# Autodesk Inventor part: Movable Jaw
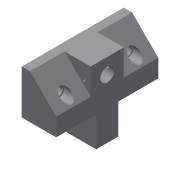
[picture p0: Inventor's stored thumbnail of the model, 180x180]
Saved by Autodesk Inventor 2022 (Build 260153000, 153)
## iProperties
Created: 2002-02
Part Number: Movable Jaw
Document SubType Name: Modeling
Designer: ***
Density: 1 g/cm^3
Material: Generic
Appearance: Default
Control State: 0
Master: False
Checked Out: False
Shininess: 77.0
Length Units: 11269
Angle Units: 11279
Time Units: 11290
Mass Units: 11283
Length Display Precision: 3
Angle Display Precision: 2
Density: 0.0
Volumn: 0.0
Area: 0.0
PropertySet Name: Model Information
Author: ***
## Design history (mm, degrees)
sketch "Sketch2"
  geometry: L1 (2.39, 41.509)-(2.39, 9.509); L2 (2.39, 9.509)-(-22.61, 9.509); L3 (-22.61, 9.509)-(-22.61, 22.509); L4 (-22.61, 22.509)-(-3.61, 41.509); L5 (-3.61, 41.509)-(2.39, 41.509)
  constraints: 10 end point, 2 parallel, 1 perpendicular, 1 vertical
  dimensions: "d0" = 25 distance of L1.end L2.end; "d2" = 13 distance of L2.end L3.end; "d3" = 32 distance between parallel lines of L5 L2; "d4" = 6 distance of L4.end L1.start
extrude "Extrusion1" new body sketch "Sketch2" stored distance "d5" = 74; taper "d6" = 0 deg
sketch "Sketch3"
  geometry: L1 (-19, 25)-(11, 25); L2 (11, 25)-(11, 49); L3 (11, 49)-(-19, 49); L4 (-19, 49)-(-19, 25); L5 (0, 0)-(13, 0) reference; L6 (-19, 74)-(-19, 0) reference; L7 (11.924, 29)-(35, 29); L8 (35, 29)-(35, 45); L9 (35, 45)-(11.924, 45); L10 (11.924, 45)-(11.924, 29); L11 (13, 74)-(13, 0) reference
  constraints: 16 end point, 4 parallel, 2 horizontal, 2 perpendicular, 1 collinear
  dimensions: "d7" = 24 distance of L3.end L1.start; "d8" = 30 distance of L1.start L1.end; "d9" = 25 distance between parallel lines of L5 L1; "d10" = 16 distance of L7.end L8.end; "d11" = 4 distance between parallel lines of L3 L9; "d12" = 22 distance between parallel lines of L11 L8
extrude "Extrusion2" join sketch "Sketch3" distance "d13" = 25; taper "d14" = 0 deg
sketch "Sketch4"
  geometry: L1 (-19, -25)-(-19, -49) reference; L2 (-19, -49)-(0, -49) reference; 1 further point
  dimensions: "d15" = 11 distance from line of L1 point (-8, -37); "d16" = 12 distance from line of L2 point (-8, -37)
hole "Hole1" sketch "Sketch4" at (-8, -37) diameter "d17" = 10; stored, may be unused: countersink angle "d21" = 82 deg, drill point angle "d23" = 0 deg; dims "d18" = 6, "d19" = 4, "d20" = 2, "d22" = 13
sketch "Sketch5"
  geometry: L1 (-19, -49)-(-19, -74) reference; L2 (0, -74)-(13, -74) reference; 1 further point
  dimensions: "d24" = 14 distance from line of L1 point (-5, -62); "d25" = 12 distance from line of L2 point (-5, -62)
hole "Hole2" sketch "Sketch5" at (-5, -62) diameter "d26" = 6; stored, may be unused: countersink angle "d30" = 82 deg, drill point angle "d32" = 0 deg; dims "d27" = 6, "d28" = 8, "d29" = 10, "d31" = 13
mirror "Mirror1"
sketch "Sketch6"
  geometry: L1 (0, 19)-(0, 0) reference; 1 further point
  dimensions: "d33" = 5 distance from line of L1 point (-5, 8); "d34" = 11 vertical distance of L1.start point (-5, 8)
hole "Hole3" sketch "Sketch6" at (-5, 8) diameter "d35" = 2; stored, may be unused: countersink angle "d39" = 82 deg, drill point angle "d41" = 0 deg; dims "d36" = 6, "d37" = 8, "d38" = 10, "d40" = 13
body "Solid1"
